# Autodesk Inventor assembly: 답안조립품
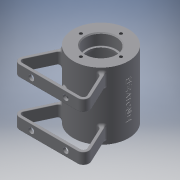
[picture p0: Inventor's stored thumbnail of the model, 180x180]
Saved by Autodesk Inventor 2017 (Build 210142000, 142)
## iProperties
Part Number: 답안조립품
Material: 일반
Document SubType Name: Assembly
Designer: Administrator
Author: Administrator
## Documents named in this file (2)
- C:\Users\Administrator\Desktop\711206V1023\답안조립품.iam
- C:\Users\Administrator\Desktop\711206V1023\본체.ipt
